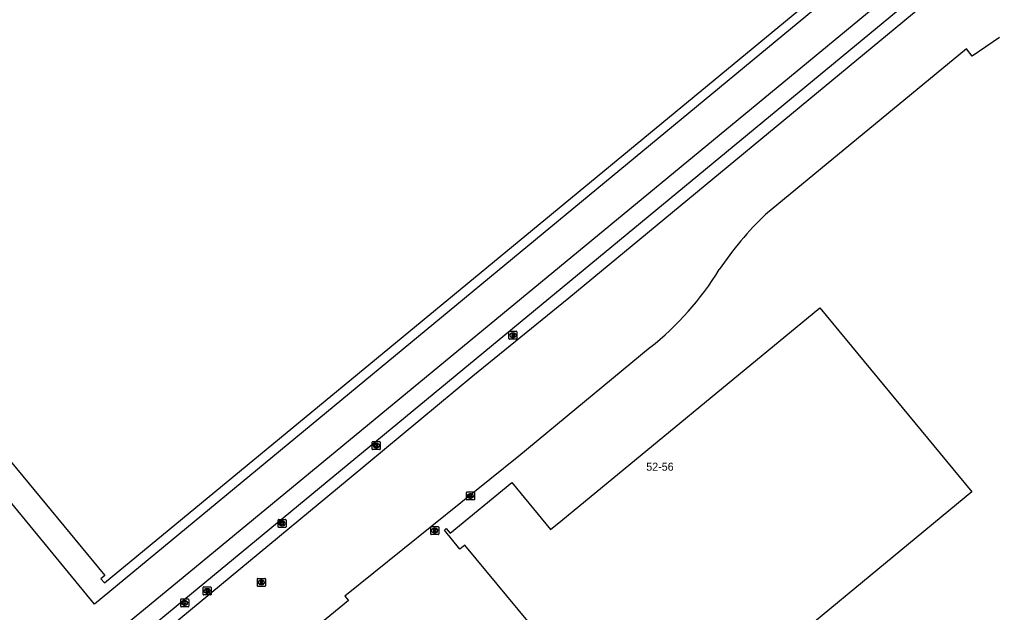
# Model space of a CAD drawing. Extents: x 156141 to 158132, y 385651 to 388399.
# Drawn here: x 157600.3 to 157722.7, y 386556.2 to 386630.3 of the extents above; entities that cross this region are included whole.
import ezdxf

# ---------------------------------------------------------------- set-up
doc = ezdxf.new("R2010")
doc.units = 0
for name, color, linetype in [('IMGEO_Brandkraan', 7, 'Continuous'), ('IMGEO_Erf', 7, 'Continuous'), ('IMGEO_Kolk', 7, 'Continuous'), ('IMGEO_Pand', 7, 'Continuous'), ('IMGEO_Pand_nummerreeks', 7, 'Continuous'), ('IMGEO_Rijbaan_lokaal_gesloten', 7, 'Continuous'), ('IMGEO_Rijbaan_lokaal_open', 7, 'Continuous'), ('IMGEO_Rioolput', 7, 'Continuous')]:
    doc.layers.add(name, color=color, linetype=linetype)

msp = doc.modelspace()

# ---------------------------------------------------------------- linework, layer by layer
at = {"layer": 'IMGEO_Brandkraan'}
for p, q in [((157661.45, 386590.46), (157661.45, 386591.31)), ((157661.52, 386591.38), (157662.37, 386591.38)), ((157662.45, 386591.31), (157662.45, 386590.46)), ((157662.37, 386590.38), (157661.52, 386590.38)), ((157661.96, 386590.6), (157661.93, 386590.6)), ((157661.94, 386591.16), (157661.96, 386591.16)), ((157623.25, 386558.5), (157623.25, 386559.35)), ((157623.32, 386559.43), (157624.18, 386559.43)), ((157624.25, 386559.35), (157624.25, 386558.5)), ((157624.18, 386558.43), (157623.32, 386558.43)), ((157623.76, 386558.65), (157623.73, 386558.65)), ((157623.74, 386559.21), (157623.76, 386559.21))]:
    msp.add_line(p, q, dxfattribs=at)
for points in [[(157661.45, 386590.46), (157661.45, 386591.31)], [(157661.52, 386591.38), (157662.37, 386591.38)], [(157662.45, 386591.31), (157662.45, 386590.46)], [(157662.37, 386590.38), (157661.52, 386590.38)], [(157661.79, 386591.08), (157661.79, 386590.68), (157662.01, 386590.68)], [(157662.03, 386591.08), (157661.79, 386591.08)], [(157661.97, 386591), (157661.92, 386591), (157661.92, 386590.93)], [(157661.92, 386590.93), (157661.97, 386590.93)], [(157661.98, 386590.85), (157661.92, 386590.85), (157661.92, 386590.77)], [(157661.92, 386590.77), (157661.98, 386590.77)], [(157623.25, 386558.5), (157623.25, 386559.35)], [(157623.32, 386559.43), (157624.18, 386559.43)], [(157624.25, 386559.35), (157624.25, 386558.5)], [(157624.18, 386558.43), (157623.32, 386558.43)], [(157623.6, 386559.13), (157623.6, 386558.73), (157623.81, 386558.73)], [(157623.83, 386559.13), (157623.6, 386559.13)], [(157623.78, 386559.05), (157623.72, 386559.05), (157623.72, 386558.97)], [(157623.72, 386558.97), (157623.78, 386558.97)], [(157623.78, 386558.89), (157623.72, 386558.89), (157623.72, 386558.81)], [(157623.72, 386558.81), (157623.78, 386558.81)]]:
    msp.add_lwpolyline(points, dxfattribs=at)
for centre, radius, start, end in [((157661.52, 386591.31), 0.0765, 91.552, 178.448), ((157661.52, 386591.31), 0.0765, 91.552, 178.448), ((157662.37, 386591.31), 0.0765, 1.552, 88.448), ((157662.37, 386591.31), 0.0765, 1.552, 88.448), ((157661.52, 386590.46), 0.0765, 181.552, 268.448), ((157661.52, 386590.46), 0.0765, 181.552, 268.448), ((157661.97, 386590.96), 0.0379, 267.8285, 90.9355), ((157661.98, 386590.81), 0.0404, 269.8759, 90.5077), ((157662.01, 386590.93), 0.251, 268.6676, 293.5347), ((157662.03, 386590.94), 0.145, 59.4692, 91.5367), ((157662.06, 386590.98), 0.0922, 285.5137, 58.1501), ((157662.06, 386590.79), 0.105, 301.3115, 78.989), ((157662.37, 386590.46), 0.0765, 271.552, 358.448), ((157662.37, 386590.46), 0.0765, 271.552, 358.448), ((157623.33, 386559.35), 0.0765, 91.552, 178.448), ((157623.33, 386559.35), 0.0765, 91.552, 178.448), ((157624.17, 386559.35), 0.0765, 1.552, 88.448), ((157624.17, 386559.35), 0.0765, 1.552, 88.448), ((157623.33, 386558.5), 0.0765, 181.552, 268.448), ((157623.33, 386558.5), 0.0765, 181.552, 268.448), ((157623.78, 386559.01), 0.0379, 267.8285, 90.9355), ((157623.78, 386558.85), 0.0404, 269.8759, 90.5077), ((157623.82, 386558.98), 0.251, 268.6676, 293.5347), ((157623.83, 386558.98), 0.145, 59.4692, 91.5367), ((157623.86, 386559.03), 0.0922, 285.5137, 58.1501), ((157623.86, 386558.84), 0.105, 301.3115, 78.989), ((157624.17, 386558.5), 0.0765, 271.552, 358.448), ((157624.17, 386558.5), 0.0765, 271.552, 358.448)]:
    msp.add_arc(centre, radius, start, end, dxfattribs=at)
for centre, major_axis, ratio, start_param, end_param in [((157661.93, 386590.88), (-0.387, 0.002), 0.722429, 4.712389, 7.853982), ((157661.96, 386590.88), (-0.39, 0.002), 0.717154, 1.570796, 4.712389), ((157623.74, 386558.93), (-0.387, 0.002), 0.722429, 4.712389, 7.853982), ((157623.76, 386558.93), (-0.39, 0.002), 0.717154, 1.570796, 4.712389)]:
    msp.add_ellipse(centre, major_axis=major_axis, ratio=ratio, start_param=start_param, end_param=end_param, dxfattribs=at)
at = {"layer": 'IMGEO_Erf'}
msp.add_lwpolyline([(157586.91, 386529.82), (157920.6, 386805.45)], dxfattribs=at)
at = {"layer": 'IMGEO_Kolk'}
for p, q in [((157644.38, 386576.66), (157644.38, 386577.51)), ((157644.45, 386577.59), (157645.31, 386577.59)), ((157645.31, 386576.59), (157644.45, 386576.59)), ((157644.89, 386576.81), (157644.86, 386576.81)), ((157644.87, 386577.37), (157644.89, 386577.37)), ((157645.38, 386577.51), (157645.38, 386576.66)), ((157656.13, 386570.36), (157656.13, 386571.21)), ((157656.21, 386571.29), (157657.06, 386571.29)), ((157656.62, 386571.07), (157656.65, 386571.07)), ((157656.64, 386570.51), (157656.62, 386570.51)), ((157657.13, 386571.21), (157657.13, 386570.36)), ((157657.06, 386570.29), (157656.21, 386570.29)), ((157632.61, 386566.94), (157632.61, 386567.79)), ((157632.69, 386567.86), (157633.54, 386567.86)), ((157633.54, 386566.86), (157632.69, 386566.86)), ((157633.1, 386567.64), (157633.13, 386567.64)), ((157633.12, 386567.08), (157633.1, 386567.08)), ((157633.62, 386567.79), (157633.62, 386566.94)), ((157620.45, 386557.01), (157620.45, 386557.86)), ((157620.52, 386557.93), (157621.38, 386557.93)), ((157621.38, 386556.93), (157620.52, 386556.93)), ((157620.96, 386557.15), (157620.93, 386557.15)), ((157620.94, 386557.71), (157620.96, 386557.71)), ((157621.45, 386557.86), (157621.45, 386557.01))]:
    msp.add_line(p, q, dxfattribs=at)
for points in [[(157644.38, 386576.66), (157644.38, 386577.51)], [(157644.45, 386577.59), (157645.31, 386577.59)], [(157645.31, 386576.59), (157644.45, 386576.59)], [(157644.7, 386577.29), (157644.82, 386577.29), (157644.82, 386577.14), (157644.95, 386577.29), (157645.12, 386577.29), (157644.97, 386577.14), (157645.12, 386576.89), (157644.97, 386576.89), (157644.89, 386577.05), (157644.82, 386576.98), (157644.82, 386576.89), (157644.7, 386576.89), (157644.7, 386577.29)], [(157645.38, 386577.51), (157645.38, 386576.66)], [(157656.13, 386570.36), (157656.13, 386571.21)], [(157656.21, 386571.29), (157657.06, 386571.29)], [(157656.45, 386570.99), (157656.58, 386570.99), (157656.58, 386570.84), (157656.71, 386570.99), (157656.87, 386570.99), (157656.73, 386570.84), (157656.88, 386570.59), (157656.73, 386570.59), (157656.64, 386570.75), (157656.58, 386570.68), (157656.58, 386570.59), (157656.45, 386570.59), (157656.45, 386570.99)], [(157657.13, 386571.21), (157657.13, 386570.36)], [(157657.06, 386570.29), (157656.21, 386570.29)], [(157632.61, 386566.94), (157632.61, 386567.79)], [(157632.69, 386567.86), (157633.54, 386567.86)], [(157633.54, 386566.86), (157632.69, 386566.86)], [(157632.93, 386567.56), (157633.06, 386567.56), (157633.06, 386567.41), (157633.19, 386567.56), (157633.35, 386567.56), (157633.21, 386567.41), (157633.36, 386567.16), (157633.21, 386567.16), (157633.12, 386567.33), (157633.06, 386567.26), (157633.06, 386567.16), (157632.93, 386567.16), (157632.93, 386567.56)], [(157633.62, 386567.79), (157633.62, 386566.94)], [(157620.45, 386557.01), (157620.45, 386557.86)], [(157620.52, 386557.93), (157621.38, 386557.93)], [(157621.38, 386556.93), (157620.52, 386556.93)], [(157620.77, 386557.63), (157620.89, 386557.63), (157620.89, 386557.48), (157621.02, 386557.63), (157621.19, 386557.63), (157621.04, 386557.48), (157621.19, 386557.23), (157621.04, 386557.23), (157620.96, 386557.4), (157620.89, 386557.33), (157620.89, 386557.23), (157620.77, 386557.23), (157620.77, 386557.63)], [(157621.45, 386557.86), (157621.45, 386557.01)]]:
    msp.add_lwpolyline(points, dxfattribs=at)
for centre, start, end in [((157644.45, 386577.51), 91.552, 178.448), ((157644.45, 386577.51), 91.552, 178.448), ((157644.45, 386576.66), 181.552, 268.448), ((157644.45, 386576.66), 181.552, 268.448), ((157645.3, 386577.51), 1.552, 88.448), ((157645.3, 386577.51), 1.552, 88.448), ((157645.3, 386576.66), 271.552, 358.448), ((157645.3, 386576.66), 271.552, 358.448), ((157656.21, 386571.21), 91.552, 178.448), ((157656.21, 386571.21), 91.552, 178.448), ((157657.06, 386571.21), 1.552, 88.448), ((157657.06, 386571.21), 1.552, 88.448), ((157656.21, 386570.36), 181.552, 268.448), ((157656.21, 386570.36), 181.552, 268.448), ((157657.06, 386570.36), 271.552, 358.448), ((157657.06, 386570.36), 271.552, 358.448), ((157632.69, 386567.79), 91.552, 178.448), ((157632.69, 386567.79), 91.552, 178.448), ((157632.69, 386566.94), 181.552, 268.448), ((157632.69, 386566.94), 181.552, 268.448), ((157633.54, 386567.79), 1.552, 88.448), ((157633.54, 386567.79), 1.552, 88.448), ((157633.54, 386566.94), 271.552, 358.448), ((157633.54, 386566.94), 271.552, 358.448), ((157620.53, 386557.86), 91.552, 178.448), ((157620.53, 386557.86), 91.552, 178.448), ((157620.53, 386557.01), 181.552, 268.448), ((157620.53, 386557.01), 181.552, 268.448), ((157621.37, 386557.86), 1.552, 88.448), ((157621.37, 386557.86), 1.552, 88.448), ((157621.37, 386557.01), 271.552, 358.448), ((157621.37, 386557.01), 271.552, 358.448)]:
    msp.add_arc(centre, 0.0765, start, end, dxfattribs=at)
for centre, major_axis, ratio, start_param, end_param in [((157644.87, 386577.09), (-0.387, 0.002), 0.722429, 4.712389, 7.853982), ((157644.89, 386577.09), (-0.39, 0.002), 0.717154, 1.570796, 4.712389), ((157656.62, 386570.79), (-0.387, 0.002), 0.722429, 4.712389, 7.853982), ((157656.64, 386570.79), (-0.39, 0.002), 0.717154, 1.570796, 4.712389), ((157633.1, 386567.36), (-0.387, 0.002), 0.722429, 4.712389, 7.853982), ((157633.13, 386567.36), (-0.39, 0.002), 0.717154, 1.570796, 4.712389), ((157620.94, 386557.43), (-0.387, 0.002), 0.722429, 4.712389, 7.853982), ((157620.96, 386557.43), (-0.39, 0.002), 0.717154, 1.570796, 4.712389)]:
    msp.add_ellipse(centre, major_axis=major_axis, ratio=ratio, start_param=start_param, end_param=end_param, dxfattribs=at)
at = {"layer": 'IMGEO_Pand'}
for points in [[(157455.9, 386748.83), (157481.74, 386717.52), (157481.15, 386717.1), (157481.56, 386716.61), (157500, 386731.81), (157510.19, 386740.21), (157546.44, 386696.25), (157517.83, 386672.67), (157518.25, 386672.17), (157518.76, 386672.65), (157545.04, 386640.72), (157544.53, 386640.32), (157544.97, 386639.85), (157561.47, 386653.46), (157593.14, 386618.42), (157574.76, 386603.67), (157575.17, 386603.16), (157575.68, 386603.58), (157610.98, 386560.84), (157610.49, 386560.43), (157610.92, 386559.93), (157704.06, 386636.85), (157656.28, 386694.78), (157662.89, 386700.24)], [(157686.9, 386544.58), (157685.44, 386543.36), (157685.02, 386543.85), (157677.57, 386537.71), (157678.05, 386537.12), (157677.78, 386536.91), (157675.84, 386539.27), (157676.46, 386539.78), (157667.2, 386550.99), (157666.59, 386550.49), (157664.59, 386552.92), (157665.21, 386553.44), (157655.94, 386564.65), (157655.33, 386564.14), (157653.38, 386566.52), (157653.62, 386566.71), (157654.12, 386566.13), (157661.82, 386572.48), (157666.65, 386566.62), (157667.92, 386567.66), (157700.29, 386594.32), (157719.28, 386571.29), (157686.9, 386544.58)]]:
    msp.add_lwpolyline(points, dxfattribs=at)
at = {"layer": 'IMGEO_Rijbaan_lokaal_gesloten'}
for points in [[(157440.18, 386618.12), (157441.67, 386615.82), (157440.11, 386614.6), (157457.92, 386601.88), (157459.5, 386601.11), (157463.42, 386599.75), (157498.16, 386588.04), (157524.18, 386556.25), (157530.12, 386556.05), (157566.08, 386512.3), (157580.69, 386514.24), (157593.9, 386524.95), (157594.57, 386534.07), (157597.97, 386536.94), (157641.49, 386572.98), (157656.95, 386585.82), (157668.95, 386595.57), (157713.76, 386632.61), (157734.89, 386649.22), (157805.11, 386707.25)], [(157722.71, 386628.09), (157719.31, 386625.75), (157718.6, 386626.66), (157693.5, 386605.96)], [(157679.07, 386589.33), (157662.67, 386575.75), (157640.97, 386558.26), (157641.4, 386557.73), (157613.7, 386534.93), (157616.05, 386532.21), (157571.02, 386494.83)]]:
    msp.add_lwpolyline(points, dxfattribs=at)
for centre, radius, start, end in [((157722.15, 386576.02), 41.44, 133.7332, 146.1855), ((157655.67, 386618.8), 37.63, 308.4436, 328.3915)]:
    msp.add_arc(centre, radius, start, end, dxfattribs=at)
at = {"layer": 'IMGEO_Rijbaan_lokaal_open'}
for points in [[(157706.31, 386644.32), (157705.86, 386640.47), (157705.22, 386636.31), (157609.67, 386557.29), (157579.2, 386594.35), (157576.46, 386594.59), (157541.32, 386637.3), (157539.43, 386641.63), (157517.25, 386668.5), (157517.83, 386668.97), (157480.31, 386714.53), (157480.05, 386714.29)], [(157712.05, 386636.08), (157710.03, 386634.29), (157620.76, 386560.6), (157609.93, 386551.71), (157610.58, 386550.88), (157596.57, 386539.37), (157586.23, 386530.59)]]:
    msp.add_lwpolyline(points, dxfattribs=at)
at = {"layer": 'IMGEO_Rioolput'}
for p, q in [((157651.68, 386566.04), (157651.68, 386566.9)), ((157651.75, 386566.97), (157652.6, 386566.97)), ((157652.16, 386566.75), (157652.19, 386566.75)), ((157652.68, 386566.9), (157652.68, 386566.04)), ((157652.6, 386565.97), (157651.75, 386565.97)), ((157652.19, 386566.19), (157652.16, 386566.19)), ((157630.03, 386559.56), (157630.03, 386560.42)), ((157630.1, 386560.49), (157630.95, 386560.49)), ((157630.95, 386559.49), (157630.1, 386559.49)), ((157630.54, 386559.71), (157630.51, 386559.71)), ((157630.52, 386560.27), (157630.54, 386560.27)), ((157631.03, 386560.42), (157631.03, 386559.56))]:
    msp.add_line(p, q, dxfattribs=at)
for points in [[(157651.68, 386566.04), (157651.68, 386566.9)], [(157651.75, 386566.97), (157652.6, 386566.97)], [(157652.68, 386566.9), (157652.68, 386566.04)], [(157652.6, 386565.97), (157651.75, 386565.97)], [(157652.26, 386566.67), (157652.01, 386566.67), (157652.01, 386566.27)], [(157652.01, 386566.27), (157652.14, 386566.27), (157652.14, 386566.43), (157652.15, 386566.43)], [(157652.19, 386566.59), (157652.14, 386566.59), (157652.14, 386566.51)], [(157652.14, 386566.51), (157652.19, 386566.51)], [(157652.19, 386566.4), (157652.27, 386566.27), (157652.4, 386566.27), (157652.34, 386566.4)], [(157630.03, 386559.56), (157630.03, 386560.42)], [(157630.1, 386560.49), (157630.95, 386560.49)], [(157630.95, 386559.49), (157630.1, 386559.49)], [(157630.62, 386560.19), (157630.36, 386560.19), (157630.36, 386559.79)], [(157630.36, 386559.79), (157630.49, 386559.79), (157630.49, 386559.95), (157630.5, 386559.95)], [(157630.54, 386560.11), (157630.49, 386560.11), (157630.49, 386560.03)], [(157630.49, 386560.03), (157630.54, 386560.03)], [(157630.55, 386559.92), (157630.62, 386559.79), (157630.76, 386559.79), (157630.69, 386559.92)], [(157631.03, 386560.42), (157631.03, 386559.56)]]:
    msp.add_lwpolyline(points, dxfattribs=at)
for centre, radius, start, end in [((157651.75, 386566.9), 0.0765, 91.552, 178.448), ((157651.75, 386566.9), 0.0765, 91.552, 178.448), ((157652.6, 386566.9), 0.0765, 1.552, 88.448), ((157652.6, 386566.9), 0.0765, 1.552, 88.448), ((157651.75, 386566.05), 0.0765, 181.552, 268.448), ((157651.75, 386566.05), 0.0765, 181.552, 268.448), ((157652.15, 386566.38), 0.0533, 26.0293, 88.6989), ((157652.2, 386566.49), 0.0964, 77.0061, 93.1865), ((157652.17, 386566.7), 0.19, 274.7715, 282.9687), ((157652.21, 386566.55), 0.0378, 276.6634, 79.6772), ((157652.26, 386566.56), 0.109, 350.3612, 89.416), ((157652.26, 386566.56), 0.112, 277.5842, 350.9817), ((157652.25, 386566.34), 0.108, 29.5134, 73.7905), ((157652.6, 386566.05), 0.0765, 271.552, 358.448), ((157652.6, 386566.05), 0.0765, 271.552, 358.448), ((157630.1, 386560.42), 0.0765, 91.552, 178.448), ((157630.1, 386560.42), 0.0765, 91.552, 178.448), ((157630.1, 386559.57), 0.0765, 181.552, 268.448), ((157630.1, 386559.57), 0.0765, 181.552, 268.448), ((157630.5, 386559.9), 0.0533, 26.0293, 88.6989), ((157630.55, 386560.01), 0.0964, 77.0061, 93.1865), ((157630.52, 386560.22), 0.19, 274.7715, 282.9687), ((157630.56, 386560.07), 0.0378, 276.6634, 79.6772), ((157630.62, 386560.08), 0.109, 350.3612, 89.416), ((157630.61, 386560.08), 0.112, 277.5842, 350.9817), ((157630.6, 386559.86), 0.108, 29.5134, 73.7905), ((157630.95, 386560.42), 0.0765, 1.552, 88.448), ((157630.95, 386560.42), 0.0765, 1.552, 88.448), ((157630.95, 386559.57), 0.0765, 271.552, 358.448), ((157630.95, 386559.57), 0.0765, 271.552, 358.448)]:
    msp.add_arc(centre, radius, start, end, dxfattribs=at)
for centre, major_axis, ratio, start_param, end_param in [((157652.16, 386566.47), (-0.387, 0.002), 0.722429, 4.712389, 7.853982), ((157652.19, 386566.47), (-0.39, 0.002), 0.717154, 1.570796, 4.712389), ((157630.51, 386559.99), (-0.387, 0.002), 0.722429, 4.712389, 7.853982), ((157630.54, 386559.99), (-0.39, 0.002), 0.717154, 1.570796, 4.712389)]:
    msp.add_ellipse(centre, major_axis=major_axis, ratio=ratio, start_param=start_param, end_param=end_param, dxfattribs=at)

# ---------------------------------------------------------------- texts
at = {"layer": 'IMGEO_Pand_nummerreeks'}
msp.add_text('52-56', height=1, dxfattribs=at).set_placement((157678.6, 386573.95))

doc.saveas('drawing.dxf')
